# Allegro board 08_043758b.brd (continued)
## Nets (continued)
GND: C1.2(N2) C2.2(N2) C3.2(N2) C4.2(N2) C5.2(N2) C6.2(N2) C7.1 C8.2(N2) C9.2(N2) C10.2(N2) C11.2(N2) C12.2(N2) C13.2(N2) C14.2(N2) C15.2(N2) C16.2(N2) C17.2(N2) C18.2(N2) C19.2(N2) C20.2(N2) C21.2(N2) C22.2(N2) C23.2(N2) C24.2(N2) C25.2(N2) C26.2(N2) C27.2(N2) C28.2(N2) C29.2(N2) C30.2(N2) C31.2(N2) C32.2(N2) C33.2(N2) C34.2(N2) C35.2(N2) C36.2(N2) C37.2(N2) C38.2(N2) C39.2(N2) C40.2(N2) C41.2(N2) C42.2(N2) C43.2(N2) C44.2(N2) C45.2(N2) C46.2(N2) C47.2(N2) C48.2(N2) C49.2(N2) C50.2(N2) C51.2(N2) C52.2(N2) C53.2(N2) C54.2(N2) C55.2(N2) C56.2(N2) C57.2(N2) C58.2(N2) C59.2(N2) C60.2(N2) C61.2(N2) C62.1 C63.1 C64.2(N2) C65.2(N2) C66.2(N2) C67.2(N2) C68.2(N2) C69.2(N2) C70.2(N2) C71.2(N2) C72.2(N2) C73.2(N2) C74.2(N2) C75.2(N2) C76.2(N2) C77.2(N2) C78.2(N2) C79.2(N2) C80.2(N2) C81.2(N2) C82.2(N2) C83.2(N2) C84.2(N2) C85.2(N2) C86.2(N2) C87.2(N2) C88.2(N2) C89.2(N2) C90.2(N2) C91.2(N2) C92.2(N2) C94.2(N2) C95.2(N2) C96.2(N2) C97.2(N2) C99.1 C100.2(N2) C101.2(N2) C102.2(N2) C103.2(N2) C104.2(N2) C105.2(N2) C106.2(N2) C107.2(N2) C108.2(N2) C109.2(N2) C110.2(N2) C111.2(N2) C112.2(N2) C113.2(N2) C114.2(N2) C115.2(N2) C116.2(N2) C117.2(N2) C118.2(N2) C119.2(N2) C120.2(N2) C121.2(N2) C122.2(N2) C124.2(N2) C125.1 C126.1 C127.2(N2) C128.2(N2) C129.1 C130.2(N2) C135.2(N2) C136.2(N2) C137.2(N2) C138.2(N2) C139.1 C140.2(N2) C141.2(N2) C142.1 C143.1 C145.2(N2) C146.2(N2) C147.1 C148.2(N2) C149.2(N2) C150.2(N2) C151.2(N2) C152.2(N2) C153.2(N2) C154.2(N2) C155.2(N2) C156.2(N2) C157.2(N2) C158.2(N2) C159.2(N2) C160.2(N2) C161.2(N2) C162.2(N2) C163.1 C164.2(N2) C165.2(N2) C166.1 C167.2(N2) C168.2(N2) C169.2(N2) C170.2(N2) C173.2(N2) C174.2(N2) C178.2(N2) D1.A(P) D2.A(P) D3.A(P) E6.1 GND.1 GND#2.1 GND#3.1 GND#4.1 L7.3 P1.7 P1.9 Q1.2(S) Q4.2(S) R2.1 R3.1 R9.2(N2) R15.2(N2) R40.2(N2) R42.2(N2) R49.1 R53.1 R54.2(N2) R61.1 R63.2(N2) R65.1 R72.2(N2) R75.2(N2) R77.2(N2) R90.2(N2) R91.2(N2) R116.2(N2) R119.2(N2) R120.2(N2) R121.2(N2) R165.2(N2) RX1A.2 RX1A.3 RX1A.4 RX1A.5(SH4) S1.3 S1.4 T1.1 T1.2 T1.5 T5.1 T5.2 T5.5 TX1A.2 TX1A.3 TX1A.4 TX1A.5(SH4) U1.6 U1.PAD U2.A9 U2.B1 U2.B3 U2.B9 U2.D1 U2.D8 U2.E1 U2.E2 U2.E8 U2.F9 U2.G1 U2.G8 U2.G9 U2.J2 U2.J8 U2.M1 U2.M9 U2.P1 U2.P9 U2.T1 U2.T9 U3.5 U3.6 U3.7 U3.8 U3.PAD U4.A1 U4.A11 U4.B8 U4.C5 U4.C15 U4.D2 U4.D12 U4.E5 U4.E7 U4.E8 U4.E9 U4.F10 U4.G3 U4.G5 U4.G13 U4.H6 U4.H8 U4.H10 U4.J5 U4.J9 U4.K4 U4.K7 U4.K10 U4.K14 U4.L1 U4.L5 U4.L11 U4.M8 U4.N5 U4.N15 U4.P2 U4.P12 U4.R9 U5.A1 U5.A2 U5.A4 U5.A5 U5.A6 U5.A12 U5.B1 U5.B2 U5.B12 U5.C1 U5.C2 U5.C4 U5.C7 U5.C8 U5.C9 U5.C10 U5.C11 U5.C12 U5.D1 U5.D12 U5.E1 U5.F1 U5.F3 U5.F7 U5.F9 U5.F11 U5.G1 U5.G10 U5.G12 U5.H1 U5.H2 U5.H3 U5.H5 U5.H6 U5.H7 U5.H9 U5.H10 U5.J1 U5.J2 U5.K1 U5.K2 U5.K12 U5.L1 U5.L2 U5.L3 U5.L7 U5.L8 U5.L9 U5.L10 U5.L11 U5.L12 U5.M4 U5.M5 U5.M6 U6.1 U6.19 U6.20 U6.21 U6.22 U6.PAD U7.6 U7.PAD U10.4 U11.4 U12.3 U12.PAD U13.B3 U14.4 U14.8 U14.PAD U15.PAD Y1.2 Y2.2 Y3.2
PGND: C171.2(N2) C172.2(N2) L7.4(N4) P2.5 P3.5 Q2.2(S) R55.2(N2) R58.2(N2) R67.2(N2) R69.2(N2) U8.C1 U9.C1 U16.B2
VCCPINT: C17.1 C19.1 C20.1 C21.1 C64.1 C66.1 C68.1 C70.1 C71.1 C72.1 C73.1 C74.1 C75.1 L4.2(N2) R7.2(N2) U4.E10 U4.F9 U4.G6 U4.G10 U4.H5 U4.J10 U4.K5 U4.L10 UNK1P0V.1
VCCPLL: C85.1 C178.1 E1.2(N2) U4.F5(VCCPLL)
VDD33_USB: C165.1 U15.20
VDD_INTERFACE: C32.1 C33.1 C38.1 C43.1 C44.1 C45.1 E4.2(N2) U5.H12
VDDA1P1_RX_VCO: C125.2(N2) R51.2(N2) U5.G2 U5.G3
VIN: C8.1 C9.1 C11.1 C62.2(N2) C135.1 C136.1 C137.1 C138.1 C157.1 C164.1 C167.1 C169.1 DS1.A(P) DS2.A(P) E2.1 Q3.2(S) R1.2(N2) R6.1 R56.1 R59.2(N2) R80.1 R81.1 R85.1 R221.1 R222.1 U3.12 U3.13 U6.14 U6.15 U6.16(VIN6) U6.25 U6.26 U6.27 U11.8(VCCB) U14.10 U15.21
VIN_5V_USB: L7.1 U8.A1 U8.B1(OUT2) U9.A1 U9.B1(OUT2)
VIN_5V_USB_DATA: F1.2(N2) P2.1 R70.1 U9.A2 U9.B2
VIN_5V_USB_POWER: P3.1 R66.1 R68.1 U8.A2 U8.B2 U16.A1
1P3_SUPPLY_A: C14.1 C15.1 C16.1 C18.1 C23.1 C24.1 C28.1 C29.1 C34.1 C35.1 C39.1 C40.1 U5.B9 U5.B10 U5.E2 U5.F2 U5.J3 U5.K3 U7.9 U7.10 U7.11 U7.12 U7.13 U7.14(VOUT5) UNK1P3V_A.1
1P3_SUPPLY_B: C3.1 C4.1 C5.1 C6.1 C26.1 C27.1 C30.1 C31.1 C36.1 C37.1 C41.1 C42.1 C129.2(N2) C130.1 E3.2(N2) L8.1 L9.1 U1.9 U1.10 U1.11 U1.12 U1.13 U1.14(VOUT5) U5.A7 U5.A8 U5.A9 U5.A10 U5.B8 U5.D2 U5.D3 U5.E3 U5.F12 U5.K4 U5.M9 U5.M10 UNK1P3V_B.1
1P8V_CLK: C121.1 C122.1 C170.1 U12.1(VOUT) UNK1P8V_CLK.1 Y3.4(VDD)
AD9363_AUXADC: ADC.1(N1) U5.L5
AD9363_AUXDAC1: DAC1.1(N1) U5.B3
AD9363_AUXDAC2: DAC2.1(N1) U5.C3
AD9363_GPO_0: GPO0.1(N1) U5.B7
AD9363_GPO_1: GPO1.1(N1) U5.B6
AD9363_GPO_2: GPO2.1(N1) U5.B5
AD9363_GPO_3: GPO3.1(N1) U5.B4
ADM1177_SCL: R81.2(N2) U10.6 U11.7
ADM1177_SDA: R80.2(N2) U10.7 U11.6
ADP2114_VIN: C141.1 R56.2(N2) U6.4 U6.8 U6.10 U6.31
COMP_1P8V: C142.2(N2) R60.1 U6.2
COMP_1P35V: C143.2(N2) C144.1 U6.7
CTRL_IN0: U4.F13 U5.C5
CTRL_IN1: U4.F14 U5.C6
CTRL_IN2: U4.G15 U5.D6
CTRL_IN3: U4.F15 U5.D5
DDR3_A0: R16.1 U2.N3 U4.P1
DDR3_A1: R22.1 U2.P7 U4.N1
DDR3_A2: R17.1 U2.P3 U4.M1
DDR3_A3: R23.1 U2.N2 U4.M4
DDR3_A4: R18.1 U2.P8 U4.P3
DDR3_A5: R24.1 U2.P2 U4.P4
DDR3_A6: R19.1 U2.R8 U4.P5
DDR3_A7: R25.1 U2.R2 U4.M5
DDR3_A8: R20.1 U2.T8 U4.P6
DDR3_A9: R26.1 U2.R3 U4.N4
DDR3_A10: R21.1 U2.L7 U4.J1
DDR3_A11: R27.1 U2.R7 U4.L2
DDR3_A12: R28.1 U2.N7 U4.M2
DDR3_A13: R34.1 U2.T3 U4.K2
DDR3_A14: R29.1 U2.T7 U4.K1
DDR3_BA0: R35.1 U2.M2 U4.M6
DDR3_BA1: R30.1 U2.N8 U4.R1
DDR3_BA2: R36.1 U2.M3 U4.N6
DDR3_CAS#: R32.1 U2.K3 U4.R5
DDR3_CK_N: R142.2(N2) U2.K7 U4.N2
DDR3_CK_P: R142.1 U2.J7 U4.N3
DDR3_CKE: R38.1 U2.K9 U4.L3
DDR3_CS#: R39.1 U2.L2 U4.R2
DDR3_DM0: U2.E7 U4.B1
DDR3_DM1: U2.D3 U4.D3
DDR3_DQ0: U2.E3 U4.D4
DDR3_DQ1: U2.F7 U4.A2
DDR3_DQ2: U2.F2 U4.C4
DDR3_DQ3: U2.F8 U4.C1
DDR3_DQ4: U2.H3 U4.B4
DDR3_DQ5: U2.H8 U4.A4
DDR3_DQ6: U2.G2 U4.C3
DDR3_DQ7: U2.H7 U4.A3
DDR3_DQ8: U2.D7 U4.E1
DDR3_DQ9: U2.C3 U4.D1
DDR3_DQ10: U2.C8 U4.E2
DDR3_DQ11: U2.C2 U4.E3
DDR3_DQ12: U2.A7 U4.F3
DDR3_DQ13: U2.A2 U4.G1
DDR3_DQ14: U2.B8 U4.H1
DDR3_DQ15: U2.A3 U4.H2
DDR3_DQS0_N: U2.G3 U4.B2
DDR3_DQS0_P: U2.F3 U4.C2
DDR3_DQS1_N: U2.B7 U4.F2
DDR3_DQS1_P: U2.C7 U4.G2
DDR3_ODT: R33.1 U2.K1 U4.K3
DDR3_RAS#: R37.1 U2.J3 U4.R6
DDR3_RST#: R42.1 U2.T2 U4.L4
DDR3_WE#: R31.1 U2.L3 U4.R3
FB0: R2.2(N2) R4.1 U3.4
FB_1P8V: R64.1 R65.2(N2) U6.32
FB_1P35V: R62.2(N2) R63.1 U6.9
IO_02_34_AD9361_CLKOUT: AD9361_CLKOUT.1(N1) U4.P8 U5.J6
IO_02_34_AD9361_RST: U4.P9 U5.K5
IO_L01_34_FB_CLK: U4.P10 U5.F10
IO_L01_34_RX_D0: U4.H14 U5.K11
IO_L01_34_RX_D1: U4.J13 U5.J12
IO_L02_34_RX_D2: U4.G14 U5.K10
IO_L02_34_RX_D3: U4.H13 U5.J11
IO_L03_34_RX_D4: U4.G12 U5.K9
IO_L03_34_RX_D5: U4.H12 U5.J10
IO_L04_34_RX_D6: U4.G11 U5.K8
IO_L04_34_RX_D7: U4.J14 U5.J9
IO_L05_34_RX_D8: U4.J15 U5.K7
IO_L05_34_RX_D9: U4.K15 U5.J8
IO_L06_34_RX_D10: U4.H11 U5.J7
IO_L06_34_RX_D11: U4.J11 U5.H8
IO_L07_34_RX_FRAME: U4.N13 U5.G8
IO_L08_34_CTRL_OUT0: U4.L15 U5.D4
IO_L08_34_CTRL_OUT1: U4.M15 U5.E4
IO_L09_34_TX_FRAME: U4.L14 U5.G9
IO_L10_34_EN_AGC: U4.L13 U5.G5
IO_L11_34_ENABLE: U4.K12 U5.G6
IO_L11_34_TXNRX: U4.K11 U5.H4
IO_L12_MRCC_34_DATA_CLK: U4.L12 U5.G11
IO_L13_34_CTRL_OUT2: U4.N11 U5.E5
IO_L13_34_CTRL_OUT3: U4.N12 U5.E6
IO_L15_34_TX_D0: U4.P15 U5.E12
IO_L15_34_TX_D1: U4.R13 U5.D11
IO_L16_34_TX_D2: U4.R15 U5.E11
IO_L16_34_TX_D3: U4.P11 U5.D10
IO_L17_34_TX_D4: U4.R11 U5.E10
IO_L17_34_TX_D5: U4.R12 U5.D9
IO_L18_34_TX_D6: U4.P14 U5.E9
IO_L18_34_TX_D7: U4.P13 U5.D8
IO_L19_34_TX_D8: U4.N9 U5.E8
IO_L19_34_TX_D9: U4.M9 U5.D7
IO_L20_34_TX_D10: U4.R8 U5.F8
IO_L20_34_TX_D11: U4.R7 U5.E7
IO_L21_34_CTRL_OUT4: U4.M10 U5.F6
IO_L21_34_CTRL_OUT5: U4.M11 U5.F5
IO_L22_34_CTRL_OUT6: U4.N7 U5.F4
IO_L22_34_CTRL_OUT7: U4.N8 U5.G4
IO_L23_35_SPI_CLK: U4.E11 U5.J5
IO_L23_35_SPI_ENB: U4.E12 U5.K6
IO_L24_35_SPI_DI: U4.E13 U5.J4
IO_L24_35_SPI_DO: U4.F12 U5.L6
JTAG_TCK: P1.4 TCK.1(N1) U4.G9
JTAG_TDI: P1.8 TDI.1(N1) U4.L7
JTAG_TDO: P1.6 TDO.1(N1) U4.L8
JTAG_TMS: P1.2 TMS.1(N1) U4.L9
PG_1P0V: R6.2(N2) R86.1 U3.16
PG_1P3V: C47.1 PG_1P3V.1(N1) R13.2(N2) R15.1 U1.5 U4.C9 U7.5 U12.4
PG_1P8V: R59.1 U6.13 U6.29
PG_1P35V: R50.1 U1.4 U6.12 U7.4
PL_GPIO0: L10P.1(N1) U4.K13
PL_GPIO1: L12N.1(N1) U4.M12
PL_GPIO2: L24N.1(N1) U4.R10
PS-SRST#: R74.2(N2) U4.B11 U13.A4
PS_GPIO0: MIO0.1(N1) U4.D8
PS_GPIO1: MIO10.1(N1) U4.B10
PS_GPIO2: MIO11.1(N1) U4.D6
PS_GPIO3: MIO09.1(N1) U4.B5
PS_GPIO4: MIO53.1(N1) U4.C13
PS_GPIO5: MIO49.1(N1) U4.D13
PS_GPIO6: MIO48.1(N1) U4.B12
PS_MIO01_500_QSPI0_SS_B: R14.2(N2) U4.A5 U13.C2
PS_MIO02_500_QSPI0_IO0: R120.1 U4.A8 U13.D3
PS_MIO03_500_QSPI0_IO1: R119.1 U4.A7 U13.D2
PS_MIO04_500_QSPI0_IO2: R121.1 U4.C8 U13.C4(W#DQ2)
PS_MIO05_500_QSPI0_IO3: JTAG_BOOT.1(N1) P1.5 R122.1 U4.A9 U13.D4
PS_MIO06_500_QSPI0_SCLK: R116.1 U4.A10 U13.B2
PS_MIO07_500_USB_RESET_B: R76.2(N2) U4.A12 U15.27
PS_MIO28_501_USB0_D4: U4.A15 U15.7
PS_MIO29_501_USB0_DIR: U4.D11 U15.31
PS_MIO30_501_USB0_STP: U4.B15 U15.29
PS_MIO31_501_USB0_NXT: U4.C12 U15.2
PS_MIO32_501_USB0_D0: U4.E15 U15.3
PS_MIO33_501_USB0_D1: U4.C11 U15.4
PS_MIO34_501_USB0_D2: U4.D15 U15.5
PS_MIO35_501_USB0_D3: U4.A14 U15.6
PS_MIO36_501_USB0_CLK: U4.B14 U15.1
PS_MIO37_501_USB0_D5: U4.C14 U15.9
PS_MIO38_501_USB0_D6: U4.A13 U15.10
PS_MIO39_501_USB0_D7: U4.D14 U15.13
PWR_CLK: R5.2(N2) R89.2(N2) R90.1 U3.1
RX1A_N: C133.2(N2) U5.M2
RX1A_P: C134.2(N2) U5.M1
SCL: R79.2(N2) U4.M14 U11.2
SDA: R78.2(N2) U4.N14 U11.3
SYNC: L4.1 U3.9 U3.10 U3.11
TX1A_N: C131.1 L8.2(N2) U5.M8
TX1A_P: C132.1 L9.2(N2) U5.M7
TX_VCO_1P1V_SUPPLY: C128.1 R52.1 U5.A11 U5.B11
UART_RX: P1.1 RX.1(N1) U4.C6
UART_TX: P1.3 TX.1(N1) U4.B7
UNNAMED_2_ADM7160V2_I254_VIN: C173.1 E2.2(N2) U12.6
UNNAMED_2_ADP1754_I93_SS: C2.1 U1.7
UNNAMED_2_ADP1754_I233_SS: C12.1 U7.7
UNNAMED_2_ADP2164_I29_EN: C13.1 R1.1 R5.1 R10.1 U3.3 U3.14(VIN) U3.15
UNNAMED_2_ADP2164_I29_RT: R3.2(N2) R10.2(N2) U3.2
UNNAMED_2_FERRITE_I303_N1: E3.1 VDD_GPO.1(N1)
UNNAMED_2_RES_I251_N2: R4.2(N2) R7.1
UNNAMED_3_ICXC7Z010_I16_PSCLK50: R12.2(N2) U4.C7
UNNAMED_3_ICXC7Z010_I16_PSMIO75: R83.2(N2) U4.D9
UNNAMED_3_ICXC7Z010_I16_PSMIO85: R84.1 U4.B6
UNNAMED_3_RES_I2_N1: R8.2(N2) R9.1 Y2.1
UNNAMED_3_RES_I48_N1: R12.1 Y2.3
UNNAMED_4_ICMT41K256M16_I98_ZQ: R165.1 U2.L8(ZQ)
UNNAMED_4_ICTPS51206_I44_S3: R222.2(N2) U14.7
UNNAMED_4_ICTPS51206_I44_S5: R221.2(N2) U14.9
UNNAMED_4_ICTPS51206_I44_VLDOIN: R44.2(N2) U14.2
UNNAMED_4_ICTPS51206_I44_VTTSNS: C80.1 R43.2(N2) U14.5(VTTSNS)
UNNAMED_4_ICXC7Z010_I26_PSDDR_1: R40.1 U4.H3
UNNAMED_4_ICXC7Z010_I26_PSDDRVR: R41.1 U4.J3
UNNAMED_5_CAP_I17_N1: C93.1 C98.1 E5.2(N2) U4.F7
UNNAMED_5_CAP_I17_N2: C93.2(N2) C98.2(N2) E6.2(N2) U4.F6 U4.F8 U4.G8 U4.H7 U4.J7
UNNAMED_5_DIOLED_I60_N: DS1.C R48.1
UNNAMED_5_DIOLED_I62_N: DS2.C R87.1
UNNAMED_5_ICXC7Z010_I13_DONE0: Q1.1 U4.M7
UNNAMED_5_ICXC7Z010_I13_INITB0: R47.1 U4.D5
UNNAMED_5_ICXC7Z010_I13_PROGRAM: R46.1 U4.K6
UNNAMED_5_ICXC7Z010_I13_VCCBATT: R45.2(N2) U4.E6
UNNAMED_5_ICXC7Z010_I13_VP0: R11.2(N2) R91.1 U4.G7
UNNAMED_5_RES_I61_N2: Q1.3 R48.2(N2)
UNNAMED_5_RES_I63_N2: Q4.3 R87.2(N2)
UNNAMED_7_AD9363_I13_RBIAS: R49.2(N2) U5.L4
UNNAMED_7_AD9363_I13_XTALN: C123.2(N2) C124.1 U5.M12(XTALN)
UNNAMED_7_CAP_I22_N2: C126.2(N2) R51.1
UNNAMED_7_CAP_I30_N1: C127.1 R52.2(N2)
UNNAMED_7_CAP_I39_N2: C132.2(N2) T5.4
UNNAMED_7_CAP_I40_N2: C131.2(N2) T5.6(SEC_DOT)
UNNAMED_7_CAP_I51_N1: C134.1 T1.4
UNNAMED_7_CAP_I52_N1: C133.1 T1.6(SEC_DOT)
UNNAMED_7_CAP_I53_N1: C123.1 Y3.3
UNNAMED_7_CNBNC5P_I57_CNTR: RX1A.1 T1.3
UNNAMED_7_CNBNC5P_I58_CNTR: T5.3 TX1A.1
UNNAMED_9_ADM1177_I23_GATE: Q3.1 U10.10
UNNAMED_9_ADM1177_I23_ON: R71.2(N2) R72.1 U10.3
UNNAMED_9_ADM1177_I23_SENSE: Q3.3 R73.2(N2) U10.2
UNNAMED_9_ADM1177_I23_SS: C155.1 U10.9
UNNAMED_9_ADM1177_I23_TIMER: C156.1 U10.5
UNNAMED_9_ADM1177_I23_VCC: D3.C L7.2 R71.1 R73.1 U10.1(VCC)
UNNAMED_9_ADP198_I329_VOUT: C171.1 C172.1 F1.1 R88.1 U16.A2(VOUT)
UNNAMED_9_ADP2114_I196_EN1: R85.2(N2) R86.2(N2) U6.28
UNNAMED_9_ADP2114_I196_FREQ: R53.2(N2) U6.3
UNNAMED_9_ADP2114_I196_OPCFG: R54.1 U6.6
UNNAMED_9_ADP2114_I196_SS1: C7.2(N2) U6.30
UNNAMED_9_ADP2114_I196_SS2: C139.2(N2) U6.11
UNNAMED_9_ADP2114_I196_SW1: L3.1 R89.1 U6.23 U6.24
UNNAMED_9_ADP2114_I196_SW3: L2.1 U6.17 U6.18
UNNAMED_9_CAP_I163_N1: C146.1 L3.2(N2) L5.1
UNNAMED_9_CAP_I214_N2: C147.2(N2) R60.2(N2)
UNNAMED_9_CAP_I224_N2: C144.2(N2) R61.2(N2)
UNNAMED_9_CHOKE4P_I327_N2: D1.C L6.2 P2.3
UNNAMED_9_CHOKE4P_I327_N3: D2.C L6.3 P2.2
UNNAMED_9_CN5P3SHLD_I255_N6: P2.SH1 P2.SH2 P2.SH3(N8) R55.1
UNNAMED_9_CN5P3SHLD_I256_N6: P3.SH1 P3.SH2 P3.SH3(N8) R58.1
UNNAMED_9_ICNCP339_I277_EN: R68.2(N2) R69.1 U8.C2
UNNAMED_9_ICNCP339_I278_EN: Q2.3 R70.2(N2) U9.C2
UNNAMED_9_RES_I270_N1: Q2.1 R66.2(N2) R67.1
UNNAMED_11_ICUSB3320C_I29_RBIAS: R77.1 U15.24
UNNAMED_11_ICUSB3320C_I29_REFCL: R82.1 U15.26
UNNAMED_11_RES_I67_N2: R82.2(N2) Y1.3
USB_ID: P2.4 U15.23
USB_OTG_CPEN: U15.17 U16.B1
USB_OTG_N: L6.4(N4) U15.19
USB_OTG_P: L6.1 U15.18
USB_VBUS_OTG: R88.2(N2) U15.22
USR_BTN: R57.2(N2) S1.1 U4.B9
USR_LED: Q4.1 R75.1 U4.D10
VTT_0P75: C79.1 C101.1 R16.2(N2) R17.2(N2) R18.2(N2) R19.2(N2) R20.2(N2) R21.2(N2) R22.2(N2) R23.2(N2) R24.2(N2) R25.2(N2) R26.2(N2) R27.2(N2) R28.2(N2) R29.2(N2) R30.2(N2) R31.2(N2) R32.2(N2) R33.2(N2) R34.2(N2) R35.2(N2) R36.2(N2) R37.2(N2) R38.2(N2) R39.2(N2) R43.1 U14.3
VTTVREF: C63.2(N2) C81.1 C84.1 C99.2(N2) C102.1 U2.H1 U2.M8 U4.F4 U14.6

Pads without a net: P3 2 3 4; S1 2 5; U1 8; U2 J1 J9 L1 L9 M7; U5 A3 G7 H11 M3 M11; U6 5; U7 8; U10 8; U11 5; U12 2 5; U13 A2 A3 A5 B1 B5 C1 C3 C5 D1 D5 E1 E2 E3 E4 E5; U15 12 15 16 25; Y1 1; Y3 1

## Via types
v1: diameter 0.508, hole 0.254, TOP to BOTTOM, 784 vias
v2: diameter 0.406, hole 0.203, TOP to BOTTOM, 592 vias

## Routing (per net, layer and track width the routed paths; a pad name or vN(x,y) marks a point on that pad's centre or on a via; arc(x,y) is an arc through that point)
1V8: length 131.4
  TOP w0.203: 41.57,9.21 41.69,9.09
  TOP w0.305: 41.57,9.21 U7.3 U7.2 ; 19.33,9.21 U1.2 ; U1.2 U1.1 ; U1.2 U1.3 19.98,9.21 ; U1.1 18.68,9.21 ; U1.1 18.25,9.98 ; U4.J6 v2(53.13,35.35) ; C25.1 31.94,12.27 ; C25.1 31.53,11.81 ; C25.1 31.53,12.72 ; U15.32 74.8,28.62 v1(74.27,29.16) ; R74.1 65.25,29.78 v1(65.25,29.54) ; U7.2 40.92,9.21 ; U7.2 U7.1 ; U11.1 56.97,15.84 C166.2 56.42,16.84 v1(56.6,17.02) ; 16.98,10.91 U1.16 ; U1.16 17.76,10.48 ; U1.16 U1.15 ; U15.14 77.3,22.44 v1(77.44,22.3) ; U4.H4 v2(54.73,36.95) ; C1.1 19.98,8.91 ; C1.1 19.98,8 ; C1.1 19.57,8.46 ; U7.16 U7.15 ; U7.16 39.35,10.48 ; U7.16 38.57,10.91 ; U4.E14 v2(57.13,28.15) ; v1(54.93,15.25) R79.1 ; U4.M13 v2(50.73,28.95) ; v1(55.34,12.77) 55.61,13.04 R78.1 ; 41.16,8.46 C10.1 ; C10.1 41.57,8.91 ; C10.1 41.57,8 ; U4.J8 v2(53.13,33.75) ; U15.11 v1(75.8,22.31) ; U4.C10 v2(58.73,31.35) ; U15.8 v1(74.1,23.44) ; R47.2 v1(65.12,39.23) ; U4.H9 v2(53.93,32.95) ; 81.51,31.82 UNK1V8.1 ; UNK1V8.1 81.51,33.35 ; UNK1V8.1 82.27,32.59 ; Y2.4 70.4,34.62 C46.1 71.54,35.19 v1(71.47,35.25) ; R84.2 66.64,38.43 v1(67.54,38.43) ; U4.J4 v2(53.13,36.95) ; U4.L6 v2(52.33,34.55) ; U4.N10 v2(49.93,31.35) ; v1(76.81,29.28) 76.8,29.28 U15.28 ; U4.B13 v2(59.53,28.95) ; U4.H15 v2(54.33,27.15) ; U4.P7 v2(49.13,34.55) ; U4.F11 v2(56.33,30.55) ; v1(75.79,29.28) 75.8,29.27 U15.30 ; 39.84,9.98 U7.1 ; U7.1 40.27,9.21 ; v1(78.97,35.89) C163.2 78.4,34.54 Y1.4 ; U13.B4 v2(73.61,45.31) ; U4.K9 v2(52.33,32.95) ; U4.J12 v2(53.13,29.75) ; U4.D7 v2(57.93,34.55) ; U4.G4 v2(55.53,36.95) ; U4.R14 v2(48.33,28.15) ; R8.1 v1(72.6,36.9) ; U4.A6 v2(60.43,34.95) ; U4.K8 v2(52.33,33.75)
  TOP w0.508: R44.1 41.3,50.89 ; R44.1 40.18,50.89 ; R44.1 40.74,50.33
  TOP w0.635: 32.42,9.66 C22.1 ; C22.1 33.06,10.36 ; C22.1 32.42,11.06 ; E4.1 34.14,12.2 ; E4.1 32.36,12.2 ; E4.1 33.25,11.38
  TOP w0.762: C82.1 39.94,46.77 ; C82.1 40.74,45.92 ; C82.1 39.94,45.07 ; C83.1 39.94,49.57 ; C83.1 40.74,48.71 ; C83.1 39.94,47.86
  TOP w1.016: 81.76,35.15 L5.2 83.12,35.93
  TOP w1.27: 84.81,33.23 C150.1 ; C150.1 84.81,35.75 ; C150.1 83.75,34.49 ; 83.75,31.44 C149.1 84.81,32.7
  BOTTOM w0.203: 82.92,34.88 v1(82.9,34.87)
  BOTTOM w0.305: C162.1 59.23,30.85 v2(58.73,31.35) 59.03,31.65 59.34,31.65 C69.1 ; C161.1 56.91,28.36 v2(57.13,28.15) ; C111.1 59.64,28.35 R76.1 ; v2(57.14,25.64) 56.96,25.46 C117.1 ; C78.1 v2(46.62,32.56) C90.1 ; v2(73.61,45.31) 73.23,45.69 C48.1 ; R64.2 84.68,35.25 ; R50.2 v1(80.36,45.03) ; v1(75.79,29.28) C154.1 ; R45.1 60.93,33.65 60.61,33.97 C53.1 60.43,34.63 v2(60.43,34.95) 60.43,35.27 C52.1 ; v1(64.23,32.84) 64.14,32.75 R83.1 ; v2(54.33,27.15) 54.35,27.16 C119.1 ; R57.1 79.81,35.89 v1(78.97,35.89) ; R13.1 73.16,32.79 v1(73.16,33.6) ; C120.1 49.13,33.85 ; C110.1 50.82,29.04 v2(50.73,28.95) 50.63,28.85 C118.1 ; C168.1 v1(76.81,29.28) C140.1 ; R14.1 v1(75.54,47.57) ; C107.1 v2(59.83,25.64) C113.1 ; C108.1 v2(46.62,30.94)
  BOTTOM w0.406: C112.1 48.33,28.65 v2(48.33,28.15) 48.33,27.64 C114.1 ; v2(59.53,28.95) 59.53,28.95 C111.1 ; C115.1 v2(57.14,25.64) ; C67.1 v2(51.93,25.64) C106.1 ; v2(43.15,30.17) 43.15,30.95 C77.1 43.57,31.42 43.17,31.82 v2(43.17,32.59) ; 49.13,33.85 49.13,33.85 v2(49.13,34.55) 48.61,34.55 48.29,34.24 C51.1 ; v2(62.83,28.45) 62.83,27.8 C103.1 62.03,27.8 v2(62.03,28.45) 62.04,28.45 C160.1 v2(62.04,29.75) C159.1 62.04,30.94 v2(62.03,30.95) 62.04,30.95 C50.1 ; C105.1 v2(54.34,25.64) C109.1 ; R46.2 50.63,32.05 v2(49.93,31.35) 49.32,31.35 C116.1
  BOTTOM w0.508: v1(65.12,39.23) 65.92,39.23 R11.1 ; v2(46.71,24.73) 45.74,24.73 C104.1 45.38,24.71 v2(44.42,24.71) ; v1(44.04,34.24) 44.04,35.73 C76.1 v1(44.02,37.16) ; v1(70.58,42.75) R122.2 ; v2(49.63,24.71) 48.68,24.71 C65.1 48.31,24.73 v2(47.34,24.73)
  BOTTOM w0.635: v1(68.3,44.9) 67.66,44.9 67.03,44.27 E5.1 67.35,43.89 v1(68.3,43.89) ; E1.1 69.59,36.35 C174.1 69.59,38.15 v1(69.38,38.36) ; C152.1 84.87,34.81 ; C152.1 84.87,33.41 ; C152.1 84.24,34.11 ; 84.24,32.59 C153.1 ; C153.1 84.87,33.28 ; C153.1 84.87,31.89
  BOTTOM w0.762: 64.2,31.32 C49.1 ; C49.1 65.25,32.57 ; C49.1 65.25,30.06 ; 65.25,29.14 C158.1 64.2,27.89
  vias: v1(18.64,8.33) v1(18.64,7.69) v1(18.64,7.06) v1(19.28,8.33) v1(19.28,7.69) v1(19.28,7.06) v1(19.91,7.69) v1(19.91,7.06) v1(33.5,11) v1(33.5,10.36) v1(33.5,9.73) v1(34.14,11) v1(34.14,10.36) v1(34.14,9.73) v1(39.6,47.32) v1(40.23,8.33) v1(40.23,7.69) v1(40.23,7.06) v1(40.49,47.32) v1(40.87,8.33) v1(40.87,7.69) v1(40.87,7.06) v1(41.37,49.35) v1(41.37,48.33) v1(41.37,47.32) v1(41.37,46.3) v1(41.37,45.29) v1(41.5,7.69) v1(41.5,7.06) v1(64.49,29.54) v1(64.88,32.84) v1(65.52,32.84) v1(65.89,29.54) v1(82.9,34.11) v1(82.9,33.35) v1(82.9,32.59) v1(82.9,31.82) v1(82.9,31.06) v1(83.54,34.87) v1(83.54,34.11) v1(83.54,33.35) v1(83.54,32.59) v1(83.54,31.82) v1(83.54,31.06)
1V35: length 42.4
  TOP w0.203: U14.1 39.22,52.23 39.34,52.11 v1(39.34,51.64)
  TOP w0.305: U2.B2 v2(60.82,55.07) ; U2.R9 v2(50.42,49.47) ; 81.63,55.45 UNK1V35.1 80.87,54.68 ; U4.E4 v2(57.13,36.95) ; U4.J2 v2(53.13,38.55) ; C60.1 63.22,38.07 v2(63.14,38.16) ; U2.H9 v2(55.22,48.67) ; U2.A1 v2(61.62,55.87) ; U2.G7 v2(56.82,51.07) ; U4.R4 v2(48.23,36.55) ; U2.K2 v2(53.62,55.07) ; U2.K8 v2(53.62,49.47) ; U2.F1 v2(57.62,55.87) ; U4.M3 v2(50.73,37.75) ; v2(55.53,39.35) 55.53,39.35 U4.F1 ; U2.D9 v2(58.42,48.67) ; U2.C9 v2(60.02,48.67) ; U2.D2 v2(59.22,55.07) ; v2(52.02,49.47) 51.62,49.07 U2.N9 ; U2.C1 v2(60.02,55.87) ; U2.A8 v2(61.62,49.47) ; U2.R1 v2(49.62,55.87) ; U2.E9 v2(57.62,48.67) ; U2.N1 v2(51.22,55.87) ; U2.H2 v2(56.02,55.07) ; U4.B3 v2(59.53,37.75)
  TOP w0.406: v2(51.73,42.15) 52.23,42.15 C58.1 ; C56.1 v1(45.82,35.27) ; v2(53.53,42.15) 54.03,42.15 C57.1
  TOP w0.635: 83.35,55.32 C151.1 83.98,54.62
  TOP w1.016: C145.1 83.86,54.21 ; C145.1 83.86,52.11 ; C145.1 82.95,53.16 ; 65.63,53.5 C100.1 ; C100.1 66.89,54.56 ; C100.1 64.37,54.56 ; 82.95,50.75 C148.1 ; C148.1 83.86,51.8 ; C148.1 83.86,49.69
  BOTTOM w0.203: v1(83.92,49.48) 84.3,49.1 R62.1
  BOTTOM w0.305: v2(50.42,49.47) 50.11,49.47 C86.1 ; UNK1V35.1 v1(82.01,55.45) ; v2(56.82,51.07) 56.3,51.07 C92.1 ; R41.2 53.63,38.55 v2(53.13,38.55) ; v2(61.62,55.87) 61.62,56.47 C88.1 ; C97.1 61.7,49.39 v2(61.62,49.47) ; C95.1 57.71,55.96 v2(57.62,55.87) ; v2(53.62,55.07) 54.22,54.47 C89.1 ; C87.1 60.63,48.67 v2(60.02,48.67) ; C91.1 55.3,48.75 v2(55.22,48.67) ; C94.1 59.84,56.05 v2(60.02,55.87) ; v2(49.62,55.87) 49.53,55.95 C96.1 ; C61.1 47.52,36.34
  BOTTOM w0.406: 47.52,36.34 47.73,36.55 v2(48.23,36.55) ; v2(55.53,39.35) 55.53,39.35 55.53,39.76 C55.1 ; v2(53.13,38.55) 53.12,38.56 C59.1
  vias: v1(64.11,54.94) v1(64.11,53.92) v1(65.12,53.29) v1(66.14,53.29) v1(82.01,54.81) v1(82.01,54.18) v1(82.01,53.54) v1(82.01,52.91) v1(82.01,52.27) v1(82.65,55.45) v1(82.65,54.81) v1(82.65,54.18) v1(82.65,53.54) v1(82.65,52.91) v1(82.65,52.27) v2(56.11,43.57) v2(56.11,42.96)
GND: length 526.8
  TOP w0.152: U5.C7 32.34,32.08 v2(29.15,32.08) ; U5.H7 28.34,32.08 v2(26.75,32.08)
  TOP w0.203: U14.8 36.29,53.03 ; v1(101.83,33.98) 101.83,34.11 102.06,34.35 D1.A 102.46,33.98 ; U5.L7 26.13,31.47 26.13,31.09 U5.L8 ; v2(39.85,53.54) 39.74,53.43 U14.4 38.35,53.43 U14.PAD ; 101.32,36.02 D2.A 100.97,35.65 v1(100.7,35.93)
  TOP w0.305: GND#4.1 60.43,10.61 ; GND#4.1 59.66,9.85 ; GND#4.1 59.66,11.38 ; GND#4.1 58.9,10.61 ; C13.2 90.07,25.21 ; C13.2 88.95,25.21 ; C13.2 89.51,25.77 ; R9.2 71.6,38.14 ; R9.2 72.06,37.73 ; R9.2 71.14,37.73 ; v1(65.62,16.63) 65.44,16.46 C167.2 ; U2.B1 v2(60.82,55.87) ; 44.51,36.26 C56.2 ; C56.2 45.63,36.26 ; C56.2 45.07,36.82 ; C58.2 52.89,43.05 ; C58.2 51.77,43.05 ; C58.2 52.33,43.61 ; U6.19 89.14,45.02 88.8,44.68 ; U6.19 89.6,44.61 ; U6.19 90.3,45.02 ; C43.2 29.84,25.88 ; C43.2 29.46,27.09 29.55,27.17 29.6,27.17 ; C43.2 29.46,25.15 C45.2 ; 29.84,25.88 v1(30.05,25.67) ; 29.84,25.88 29.87,25.88 ; v1(34.77,53.1) 34.9,53.22 C84.2 35.6,53.03 36.29,53.03 ; U5.L7 v2(26.75,32.08) ; v2(33.14,27.28) U5.C12 v2(33.14,28.08) U5.C11 v2(33.14,28.88) U5.C10 v2(33.14,29.68) U5.C9 v2(33.14,30.48) U5.C8 v2(33.14,31.28) U5.C7 ; U5.H2 v2(28.35,36.08) U5.J2 ; 87.06,20.9 U3.6 ; U3.6 U3.7 ; U3.6 89.46,20.9 v2(89.78,20.57) 89.46,20.25 U3.7 ; U3.6 U3.5 ; C62.1 37.37,51.46 ; C62.1 37.37,50.54 ; C62.1 37.78,51 ; U4.R9 v2(48.25,32.55) ; U5.C2 v2(33.14,36.08) U5.B2 ; U2.T1 v2(48.82,55.87) 48.82,56.16 ; U4.A11 v2(60.53,30.95) ; U5.D1 v2(32.34,36.88) ; C12.2 45.13,11.57 ; C12.2 44.68,11.16 ; C12.2 44.05,11.57 v1(44.04,11.56) U7.6 41.57,11.56 v2(41.25,11.88) ; U4.B8 v2(58.73,33.75) ; U2.P1 v2(50.42,55.87) 50.42,56.18 ; 87.06,19.6 U3.8 ; U3.8 U3.7 ; U3.8 88.72,19.6 v2(88.76,19.56) ; C124.2 24.29,24.79 ; C124.2 24.29,23.87 ; C124.2 23.89,24.33 ; GND#3.1 35.34,65.22 ; GND#3.1 34.26,64.14 ; GND#3.1 33.18,65.22 ; GND#3.1 34.26,66.3 ; C167.2 65.85,16.01 ; C167.2 65.44,15.55 ; U5.D12 v2(32.34,27.28) ; U5.A4 v2(34.85,34.08) ; U6.22 88.94,43.52 88.8,43.66 ; U6.22 89.6,43.93 ; U6.22 90.3,43.52 ; U13.B3 v2(73.62,46.29) ; U4.E5 v2(57.13,36.15) ; C2.2 22.46,11.57 v1(22.45,11.56) U1.6 19.98,11.56 v2(19.66,11.88) ; C2.2 23.09,11.16 ; C2.2 23.54,11.57 ; U5.C4 v2(33.14,34.48) ; U2.E8 v2(58.42,49.47) ; 29.6,27.17 29.54,27.23 U5.G12 ; 29.6,27.17 29.62,27.17 v2(29.65,27.15) ; U2.J8 v2(55.22,49.47) ; U4.N5 v2(49.93,36.15) ; U4.E8 56.73,33.35 v2(56.33,33.75) U4.E7 ; U2.E2 v2(58.42,55.07) ; 22.11,34.62 R49.1 ; R49.1 22.52,34.16 ; R49.1 22.52,35.08 ; U3.5 88.72,21.55 v2(88.76,21.59) ; U3.5 87.06,21.55 ; U3.5 87.81,21.98 ; U3.7 87.06,20.25 ; U4.L11 v2(51.53,30.55) ; U5.L8 v2(25.95,30.48) U5.L9 v2(25.95,29.68) U5.L10 v2(25.95,28.88) U5.L11 v2(25.95,28.08) U5.L12 v2(25.95,27.28) 25.95,26.5 ; 30.49,12.27 C25.2 ; U5.F3 v2(30.74,35.28) ; 76.55,54.24 GND#2.1 ; GND#2.1 77.76,55.45 ; GND#2.1 76.55,56.65 ; GND#2.1 75.35,55.45 ; U5.K2 v2(26.74,36.08) U5.L2 ; U2.A9 v2(61.62,48.67) ; U5.E1 v2(30.74,36.88) U5.F1 ; 29.64,24.42 C45.2 ; C45.2 30.2,24.98 ; R61.1 98.2,42.5 ; R61.1 97.64,41.95 ; R61.1 97.08,42.5 ; C16.2 40.23,17.18 ; U4.P12 v2(49.13,29.75) ; C60.2 63.86,38.07 v2(63.94,38.16) ; 77.1,31.75 Y1.2 ; Y1.2 77.1,33.35 ; Y1.2 76.35,32.55 ; 17.55,38.19 T1.1 ; T1.1 18.8,38.2 ; T1.1 16.93,39.28 ; 102.36,11.26 Q4.2 ; Q4.2 104.27,11.26 ; Q4.2 103.31,12.02 ; Q4.2 103.31,10.5 ; 14.88,28.36 T5.1 ; 102.36,17.93 Q1.2 ; Q1.2 103.31,17.17 ; Q1.2 104.27,17.93 ; Q1.2 103.31,18.69 ; 72.17,34.16 C46.2 ; C46.2 72.58,34.62 ; C46.2 72.17,35.19 v1(72.24,35.25) ; U5.F9 v2(30.74,29.68) ; v2(60.33,39.35) U4.A1 ; U4.K7 v2(53.13,34.55) ; U5.H6 v2(28.35,32.88) ; U5.L1 v2(26.74,36.88) U5.K1 ; U5.M6 v2(25.14,32.88) U5.M5 ; U2.G8 v2(56.82,50.27) ; 93.38,6.8 GND.1 ; GND.1 95.79,6.8 ; GND.1 94.59,5.6 ; GND.1 94.59,8.01 ; v1(82.52,26.36) 82.27,26.11 C164.2 ; U4.C15 v2(58.33,27.24) ; 40.27,56.17 C79.2 ; C79.2 41.97,56.17 ; C79.2 41.12,56.97 ; 107.25,28.53 S1.4 108.03,27.58 ; U4.K10 v2(52.33,31.35) ; U4.K14 v2(53.13,28.94) ; 66.65,5.38 P1.7 ; U6.1 94.81,42.52 v1(95.35,41.98) ; U5.G10 v2(29.95,29.68) ; C1.2 v1(21.18,8.46) ; 54.13,43.6 C57.2 53.57,43.05 ; U4.M8 v2(50.73,33.75) ; 48.29,14 U12.3 47.61,14.41 ; 13.8,30.27 T5.2 ; C5.2 18.64,17.18 ; U5.K12 v2(26.74,27.28) ; 91.62,15.5 C8.2 91.16,15.1 ; U5.H9 v2(29.15,30.48) ; U4.C5 v2(58.73,35.35) ; 59.17,13.89 U11.4 v1(58.25,13.23) ; U4.N15 v2(50.33,27.25) ; U2.B9 v2(60.02,49.47) ; U4.E9 v2(57.13,32.15) ; U4.H6 v2(53.93,35.35) U4.J5 ; U5.L3 v2(25.95,35.28) ; v2(52.02,48.67) 52.42,49.07 U2.M9 ; U5.A2 v2(34.74,36.08) ; U4.H8 54.33,33.35 v2(53.93,33.75) ; 50.42,48.23 v2(50.42,48.67) U2.P9 ; U2.J2 v2(55.22,55.07) ; U2.D8 v2(58.42,50.27) ; U5.A5 v2(34.85,33.28) ; R75.2 101.57,14.53 ; R75.2 101.01,13.97 ; R75.2 102.13,13.97 ; U5.B12 v2(33.94,27.28) ; U2.G1 v2(56.82,55.87) ; U4.D2 v2(57.93,38.55) ; U4.G13 v2(55.53,28.95) ; U4.G5 v2(55.53,36.15) ; 77.76,36.35 C163.1 v1(77.23,35.89) ; U5.A6 v2(34.85,32.48) ; C33.2 31.21,17.09 v1(30.96,16.84) ; U5.B1 v2(33.14,36.88) U5.C1 ; 20.32,38.79 T1.5 ; U4.D12 v2(57.93,29.75) ; U5.A1 v2(34.74,36.88) ; U5.A12 v2(34.74,27.28) ; U5.J1 v2(28.35,36.88) U5.H1 ; 52.02,56.18 v2(52.02,55.87) U2.M1 ; C6.2 19.91,17.18 ; 55.38,16.39 C166.1 ; 107.25,23.03 S1.3 108.03,23.98 ; U4.J9 v2(53.13,32.95) ; 81.57,25.65 C164.2 ; C164.2 81.57,26.57 ; U5.H3 v2(28.35,35.28) ; U2.G9 v2(56.82,48.67) ; U5.H5 v2(28.35,33.68) ; U2.F9 v2(56.82,49.47) ; v1(62.33,34.11) 62.58,33.86 v1(65.14,33.86) v1(66.24,33.86) 70.8,33.86 v1(71.13,33.53) ; U4.P2 v2(49.13,38.55) ; U5.F7 v2(30.74,31.28) ; C122.2 26.1,16.08 ; 96.11,41.95 R53.1 96.67,42.5 ; U5.M4 v2(25.14,34.48) ; U2.T9 v2(48.82,48.67) 48.82,48.51 ; U2.B3 v2(60.82,53.47) ; C10.2 v1(42.77,8.46) ; U4.K4 v2(52.33,36.95) ; U2.E1 v2(58.42,55.87) ; U2.D1 v2(59.22,55.87) ; 67.92,5.38 P1.9 ; U4.L1 v2(51.93,39.45) ; U5.G1 v2(29.14,36.88) ; U4.L5 v2(51.53,36.15) ; C18.2 41.5,17.18 ; 17.57,40.38 T1.2 19.44,39.3 ; U4.H10 v2(54.73,31.35) ; U5.H10 v2(29.15,29.68) ; U5.F11 v2(30.74,28.08) ; U4.F10 v2(56.33,31.35) ; C141.2 97.55,46.81 ; U4.G3 v2(55.53,37.75) ; U5.H7 v2(29.15,32.08)
  TOP w0.406: v2(51.73,42.95) 52.23,42.95 C58.2 ; C57.2 53.93,42.85 v2(53.53,42.85)
  TOP w0.508: C121.2 27.53,14.55 ; C121.2 26.73,13.7 ; C121.2 26.73,15.4 ; C143.1 v1(96.86,44.54) ; 49.9,12.06 C169.2 ; C169.2 49.9,13.23 ; C169.2 49.35,12.65 ; 68.27,37.1 Y2.2 67.47,36.35 ; 46.58,14.02 C170.2 ; 56.43,20.58 C68.2
  TOP w0.635: 31.02,15.25 C32.2 ; C32.2 30.39,15.95 ; C32.2 31.02,16.65 ; 30.39,10.36 C22.2 31.02,9.66 ; v1(13.58,29) T5.1 v1(16.46,29) ; T1.5 19.89,39.04 ; 49.38,16.11 v1(49.38,15.06) 49.38,14.01 ; C3.2 14.9,15 ; C3.2 14.26,14.3 ; C3.2 14.9,13.6 ; v1(16.75,39.38) T1.1 v1(19.17,37.99) ; C4.2 17.82,17.41 ; C4.2 16.42,17.41 ; C4.2 17.12,18.04 ; v1(16.71,40.31) 16.88,40.48 17.4,40.48 T1.2 19.6,39.21 v1(19.71,38.81) ; 36.49,13.6 C15.2 ; C15.2 36.49,15 ; C15.2 35.85,14.3 ; C14.2 38.71,18.04 ; C14.2 38.01,17.41 ; C14.2 39.41,17.41 ; v1(13.07,29.71) 13.58,30.22 14.82,30.22 T5.2 16.13,30.27 v1(16.48,29.92) 16.83,30.27 T5.5 ; 49.57,16.65 C173.2 ; C173.2 48.93,17.35 ; C173.2 49.57,18.04 ; C9.2 93.38,15 ; C9.2 91.98,15 ; C9.2 92.68,14.36 ; 85.38,54.62 C151.2 86.02,55.32
  TOP w0.762: 60.64,19.7 C64.2 ; C64.2 63.16,19.7 ; C64.2 61.9,18.64 ; 37.44,45.92 C82.2 ; C82.2 38.24,46.77 ; C82.2 38.24,45.07 ; 27.81,20.07 Y3.2 26.96,21.02 ; C100.2 66.89,57.35 ; C100.2 65.63,58.41 ; C100.2 64.37,57.35 ; C19.2 77.57,20.6 ; C19.2 78.62,19.7 ; C19.2 76.52,19.7 ; C17.2 82.65,20.6 ; C17.2 81.6,19.7 ; C17.2 83.7,19.7 ; 88.17,39.7 C135.2 88.81,39 ; 88.17,37.92 C137.2 ; C137.2 88.81,37.22 ; C137.2 88.81,38.62 ; C54.2 61.27,43.06 ; C54.2 60.21,44.32 ; C54.2 60.21,41.81 ; 87.92,50.62 C138.2 ; C138.2 88.56,49.92 ; C138.2 88.56,51.32 ; 38.24,47.86 C83.2 ; C83.2 38.24,49.57 ; C83.2 37.44,48.71 ; C21.2 86.24,19.7 ; C21.2 84.14,19.7 ; C21.2 85.19,20.6 ; C71.2 59.9,19.76 ; C71.2 58.65,18.7 ; C71.2 57.39,19.76 ; C81.2 39.04,55.83 ; C81.2 38.14,54.77 ; C81.2 38.14,56.88 ; C20.2 81.16,19.7 ; C20.2 79.06,19.7 ; C20.2 80.11,20.6 ; 87.92,48.84 C136.2 88.56,49.54 ; C157.2 85.05,61.8 ; C157.2 83.79,62.85 ; C157.2 82.54,61.8 ; 37.95,54.04 U14.PAD v1(37.95,51.76)
  TOP w1.016: 85.76,52.11 C145.2 ; C145.2 85.76,54.21 ; C145.2 86.66,53.16 ; 85.76,51.8 C148.2 86.66,50.75 ; 94.97,13.84 C11.2 ; C11.2 93.91,14.74 ; C11.2 96.02,14.74 ; C146.2 87.73,37.67
  TOP w1.27: C149.2 88.66,31.44 ; C149.2 87.6,30.18 ; C149.2 87.6,32.7 ; C150.2 87.6,35.75 ; C150.2 87.6,33.23 ; C150.2 88.66,34.49 ; 92.38,54.81 D3.A ; D3.A 94.77,54.81 ; D3.A 93.57,53.41
  L5_SIG w0.305: GND#3.1 34.26,66.3 ; GND#3.1 33.18,65.22 ; GND#3.1 35.34,65.22 ; GND#3.1 34.26,64.14 ; 93.38,6.8 GND.1 ; GND.1 94.59,8.01 ; GND.1 94.59,5.6 ; GND.1 95.79,6.8 ; GND#4.1 60.43,10.61 ; GND#4.1 59.66,11.38 ; GND#4.1 58.9,10.61 ; GND#4.1 59.66,9.85 ; GND#2.1 76.55,56.65 ; GND#2.1 76.55,54.24 ; GND#2.1 77.76,55.45 ; GND#2.1 75.35,55.45
  L6_SIG w0.305: 58.9,10.61 GND#4.1 ; GND#4.1 59.66,9.85 ; GND#4.1 59.66,11.38 ; GND#4.1 60.43,10.61 ; 66.65,5.38 P1.7 ; 67.92,5.38 P1.9 68.71,6.17 ; 75.35,55.45 GND#2.1 ; GND#2.1 76.55,54.24 ; GND#2.1 76.55,56.65 ; GND#2.1 77.76,55.45 ; GND.1 95.79,6.8 ; GND.1 94.59,8.01 ; GND.1 93.38,6.8 ; GND.1 94.59,5.6 ; GND#3.1 34.26,66.3 ; GND#3.1 34.26,64.14 ; GND#3.1 33.18,65.22
  BOTTOM w0.305: v2(59.22,55.87) 59.21,55.88 C94.2 58.8,56.48 ; 77.84,28.19 R77.2 77.84,27.07 ; 55.17,40.95 C55.2 ; C55.2 55.73,41.51 ; C55.2 56.29,40.95 ; v1(46.84,57.48) 46.45,57.48 46.21,57.24 R42.2 ; 33.18,65.22 GND#3.1 ; GND#3.1 35.34,65.22 ; GND#3.1 34.26,64.14 ; GND#3.1 34.26,66.3 ; 53.27,41.25 R40.2 ; R40.2 53.63,41.05 v2(53.13,41.05) ; R40.2 54.39,41.25 ; C42.2 33.14,34.66 v2(33.14,34.48) ; R3.1 91.46,22.57 ; R3.1 90.9,22.01 ; R3.1 90.35,22.57 ; 37.7,26.37 C127.2 37.14,25.81 ; v1(88.11,25.09) R2.1 ; R2.1 87.55,24.32 ; R2.1 88.67,24.32 ; C91.2 55.3,49.39 v2(55.22,49.47) ; C91.2 55.82,49.8 ; C91.2 56.28,49.39 ; 60.43,30.85 60.46,30.85 ; 60.43,30.85 C162.2 60.05,30.39 ; 60.43,30.85 v2(60.53,30.95) ; 94.59,5.6 GND.1 ; GND.1 93.38,6.8 ; GND.1 95.79,6.8 ; GND.1 94.59,8.01 ; 56.08,24.83 C117.2 ; C117.2 56.53,24.42 ; C117.2 56.96,24.83 v2(57.14,24.65) ; 60.53,31.29 C69.2 61.09,31.85 ; 50.63,27.42 C118.2 50.17,27.83 ; 59.44,34.6 C178.2 58.88,35.16 ; 68.71,6.17 P1.9 67.92,5.38 ; 59.66,9.85 GND#4.1 ; GND#4.1 60.43,10.61 ; GND#4.1 58.9,10.61 ; GND#4.1 59.66,11.38 ; C36.2 25.04,32.85 ; C36.2 23.92,32.85 ; C36.2 24.48,32.29 ; 25.94,38.43 C29.2 25.38,37.87 ; C23.2 32.05,36.58 v2(32.34,36.88) ; 71.14,37.41 C174.2 70.58,37.97 ; 48.67,33.03 C120.2 49.13,32.63 ; C90.2 45.63,33.71 ; C90.2 45.07,33.15 ; C90.2 v2(45.63,32.56) C78.2 ; 78.98,22.34 C165.2 ; C165.2 79.83,23.14 ; C165.2 78.13,23.14 ; 58.97,27.25 C111.2 ; C111.2 59.53,26.69 ; C111.2 60.09,27.25 ; C114.2 47.43,28.11 ; C114.2 47.52,27.64 v2(47.52,28.14) 47.52,28.66 C112.2 47.43,29.34 47.43,29.34 ; C114.2 47.43,26.99 ; v2(30.74,35.28) C125.1 ; v1(77.57,31.05) C140.2 76.81,31.61 ; R72.2 92.39,56.66 ; R72.2 91.08,56.66 ; R72.2 91.83,56.1 ; GND#2.1 76.55,56.65 ; GND#2.1 77.76,55.45 ; GND#2.1 76.55,54.24 ; GND#2.1 75.35,55.45 ; C39.2 28.16,36.08 v2(28.35,36.08) ; 56.35,56.34 C63.1 56.76,55.88 ; 35.53,32.88 C31.2 34.97,32.32 ; 92.38,46.19 C139.1 ; C139.1 92.94,45.63 ; C139.1 93.5,46.19 ; 83.25,43.39 R90.2 ; R90.2 83.81,43.93 ; R90.2 84.37,43.39 ; 58.3,24.65 C115.2 57.74,24.09 ; C156.2 88.92,56.57 ; C156.2 88.37,56.01 ; C156.2 88.92,55.19 ; 52.72,32.61 C72.2 53.28,32.05 ; C44.2 29.46,28.14 ; C44.2 29.46,27.33 v2(29.65,27.15) 29.64,27.14 C38.2 29.64,25.91 ; C44.2 29.87,27.68 ; 60.73,50.12 C87.2 60.17,49.56 ; 60.53,24.09 C107.2 ; C107.2 v2(59.83,24.65) C113.2 ; C107.2 61.09,24.65 ; v2(48.82,48.67) 49.52,48.67 C86.2 49.92,48.67 v2(50.42,48.67) ; 56.53,27.32 C161.2 56.07,27.73 ; 94.46,43.34 R54.2 93.9,43.9 ; 54.63,31.39 C74.2 ; C74.2 54.63,32.51 ; C74.2 54.07,31.95 ; C119.2 54.35,26.53 v2(54.33,26.55) ; v1(94.59,39.76) C7.1 93.83,39.35 ; 33.95,33.82 C37.2 34.51,34.38 ; C26.2 31.77,26.68 ; C28.2 30.85,38.14 ; 40.23,55.92 C80.2 39.77,55.51 ; R15.2 71.27,32.65 C47.2 72.24,33.06 ; R15.2 70.66,32.7 ; R15.2 71.22,33.26 ; U10.4 v1(88.75,58.05) ; 49.22,29.89 C116.2 48.67,30.45 ; v1(53.72,44.87) R165.2 ; R65.1 93.95,42.91 ; R65.1 93.39,42.35 ; R65.1 94.51,42.35 ; 59.13,24.09 C113.2 ; C113.2 58.57,24.65 ; 72.65,46.33 C48.2 ; C48.2 73.59,46.33 v2(73.62,46.29) ; C48.2 73.11,46.73 ; 61.65,34.45 C53.2 61.25,34.91 ; 25.55,34.81 C41.2 26.01,35.21 v2(25.95,35.28) 25.83,35.4 25.62,35.4 ; 45.07,31.95 C78.2 ; C78.2 45.63,31.39 ; 51.33,24.09 C106.2 ; 30.3,38.67 C126.1 29.19,38.67 ; C88.2 60.82,56.49 v2(60.82,55.87) ; 74.19,50.1 R116.2 73.07,50.1 ; 55.59,24.65 C105.2 55.03,24.09 ; v2(33.14,30.48) 33.23,30.56 C27.2 33.23,31.2 v2(33.14,31.28) ; 25.62,35.4 C24.2 25.22,35.88 ; 25.62,35.4 25.62,35.38 ; 83.4,57.55 C155.2 83.96,56.77 ; 54.73,33.1 C70.2 54.17,33.66 ; 93.74,46.17 R63.2 94.14,45.84 93.76,45.46 93.3,45.46 v2(93.27,45.49) ; 95.57,41.73 C147.1 96.12,41.17 ; R121.2 72.16,43.52 ; v2(48.82,55.87) 48.9,55.95 C96.2 ; 53.63,24.09 C109.2 ; C108.2 v2(45.63,30.94) ; C108.2 45.07,30.35 ; C108.2 45.63,29.79 ; 62.23,48.35 C97.2 61.7,48.75 v2(61.62,48.67) ; 46.54,34.24 C51.2 47.1,34.8 ; 55.76,50.35 C92.2 ; C92.2 56.22,49.95 ; C92.2 56.68,50.35 ; v2(33.14,28.88) 33.23,28.96 C40.2 33.23,29.6 v2(33.14,29.68) ; v2(52.02,48.67) 52.5,49.15 C102.2 ; 57.92,39.04 C99.1 58.38,39.45 ; 55.32,53.91 C89.2 55.22,54.57 v2(55.22,55.07) ; 51.97,39.55 C59.2 52.53,40.11 ; 51.53,27.49 C110.2 ; 58.75,56.48 C95.2 58.34,55.95 v2(58.42,55.87) ; 47.52,35.13 C61.2 ; C30.2 32.45,25.78 ; C30.2 31.89,26.34 ; C30.2 31.89,25.22 ; R119.2 68.82,48.77 ; 57.23,32.29 C75.2 57.79,32.85 ; 21.64,26.43 C129.1 21.18,26.02 ; 42.86,57.6 C101.2 ; C101.2 43.42,58.16 ; C101.2 43.42,57.05 ; 76.81,27.09 C168.2 ; C142.1 97.67,43.76 ; 66.65,5.38 P1.7 ; 68.82,46.63 R120.2 ; 52.53,24.09 C67.2 ; 75.23,27.65 C154.2 75.79,27.09 ; 35.25,26.95 C128.2 ; C34.2 28.44,38.14 ; 54.02,35.59 C73.2 ; 61.25,34.99 C52.2
  BOTTOM w0.406: C106.2 v2(51.93,24.65) C67.2 ; C160.2 v2(63.03,29.74) C159.2 v2(63.03,30.95) 63.03,30.95 C50.2 ; v2(30.74,36.88) 30.74,37.47 C28.2 ; v2(51.93,39.45) 52.43,39.45 C59.2 ; v2(34.74,27.28) 34.82,27.35 C128.2 ; v2(52.33,31.35) 52.63,31.65 52.63,31.95 C72.2 ; C115.2 v2(57.14,24.65) ; C66.2 53.83,29.65 v2(53.13,28.94) ; C105.2 v2(54.34,24.65) C109.2 ; C127.2 v1(37.14,27.17)
  BOTTOM w0.508: C35.2 v1(36.45,29.87) ; v1(68.04,47.19) R120.2 ; 29.74,39.48 C126.1 ; v1(70.58,39.57) 70.27,39.25 R91.2 ; v1(73.63,50.87) R116.2 ; C142.1 97.12,44.28 v1(96.86,44.54) ; v1(71.6,42.75) R121.2 ; v2(28.35,36.88) 28.35,37.49 C34.2 ; v1(68.04,48.21) R119.2 ; C29.2 v1(26.64,37.87)
  BOTTOM w0.635: E6.1 72.56,40.84 ; E6.1 71.73,39.95 ; E6.1 71.73,41.73 ; C85.2 65.69,35.95 v1(66.94,35.95) ; C152.2 86.9,34.11 ; C152.2 86.27,34.81 ; C152.2 86.27,33.41 ; 86.27,31.89 C153.2 ; C153.2 86.27,33.28 ; C153.2 86.9,32.59
  BOTTOM w0.762: 41.71,30.37 C77.2 ; C77.2 41.71,32.47 ; C77.2 40.81,31.42 ; 68.04,26.63 68.04,27.89 ; 68.04,27.89 69.1,27.89 ; 68.04,27.89 68.04,29.14 ; 45.57,22.09 C104.2 ; C104.2 44.51,23 ; C104.2 46.62,23 ; 63.49,25.49 C103.2 62.43,24.59 ; 68.04,30.06 68.04,31.32 ; 68.04,31.32 69.1,31.32 ; 68.04,31.32 68.04,32.57 ; 19.78,24.27 C130.2 ; C130.2 19.09,24.9 ; C130.2 20.48,24.9 ; 40.17,35.75 C76.2 ; C76.2 41.22,34.49 ; C76.2 41.22,37.01 ; 48.49,22.09 C65.2 ; C65.2 49.54,23 ; C65.2 47.43,23
  vias: v1(1.6,24.71) v1(1.57,21.18) v1(2.42,48.15) v1(2.59,44.62) v1(2.59,21.18) v1(2.87,24.71) v1(3.15,58.24) v1(3.15,53.16) v1(3.15,39.19) v1(3.15,34.11) v1(3.15,16.33) v1(3.15,11.25) v1(3.69,48.15) v1(3.86,44.62) v1(3.86,21.18) v1(4.14,24.71) v1(4.96,48.15) v1(5.13,44.62) v1(5.13,21.18) v1(5.41,24.71) v1(5.69,55.7) v1(5.69,36.65) v1(5.69,31.57) v1(5.69,13.79) v1(5.69,8.71) v1(6.23,48.15) v1(6.4,44.62) v1(6.4,21.18) v1(6.68,24.71) v1(7.5,48.15) v1(7.44,21.18) v1(7.67,44.62) v1(7.92,24.96) v1(8.23,58.24) v1(8.23,53.16) v1(8.23,39.19) v1(8.23,34.11) v1(8.23,16.33) v1(8.23,11.25) v1(8.23,6.17) v1(8.64,28.55) v1(8.64,27.28) v1(8.64,26.01) v1(8.7,21.38) v1(8.77,48.15) v1(8.83,29.81) v1(8.94,44.61) v1(9.34,30.97) v1(9.83,21.95) v1(10.03,47.99) v1(10.11,44.12) v1(10.13,31.96) v1(10.77,55.7) v1(10.77,50.62) v1(10.77,41.73) v1(10.77,36.65) v1(10.77,22.81) v1(10.77,18.87) v1(10.77,13.79) v1(10.77,8.71) v1(11.22,47.55) v1(11.21,43.48) v1(11.16,32.71) v1(11.57,23.8) v1(12.05,24.98) v1(12.21,28.78) v1(12.17,27.51) v1(12.17,26.24) v1(12.32,46.92) v1(12.31,42.85) v1(12.34,33.17) v1(13.31,39.19) v1(13.31,21.41) v1(13.31,16.33) v1(13.31,11.25) v1(13.31,6.17) v1(13.42,46.28) v1(13.41,42.21) v1(13.61,33.3) v1(14.07,14.3) v1(14.2,28.01) v1(14.52,45.65) v1(14.51,41.58) v1(14.88,33.3) v1(15.09,15.31) v1(15.47,28.01) v1(15.62,45.01) v1(15.61,40.94) v1(15.85,50.62) v1(15.85,23.95) v1(15.85,18.87) v1(15.85,3.63) v1(16.1,17.35) v1(16.15,33.3) v1(16.72,44.38) v1(16.74,28.01) v1(16.86,38.3) v1(17.12,18.36) v1(17.42,33.3) v1(17.63,27.51) v1(17.82,43.74) v1(18.01,37.67) v1(18.01,17.47) v1(18.39,48.08) v1(18.69,33.3) v1(18.64,24.71) v1(18.92,43.11) v1(18.9,27.51) v1(19.02,17.47) v1(19.15,36.78) v1(19.78,35.89) v1(19.78,23.7) v1(19.91,27.51) v1(20.02,42.47) v1(19.96,33.3) v1(20.04,17.47) v1(20.67,35.38) v1(20.93,60.78) v1(20.93,50.62) v1(20.93,45.54) v1(20.93,24.71) v1(20.93,18.87) v1(20.93,3.63) v1(21.18,41.73) v1(21.18,25.73) v1(21.82,35.25) v1(22.45,40.97) v1(23.21,19.38) v1(23.47,48.08) v1(23.47,40.08) v1(23.47,16.33) v1(23.47,6.17) v1(23.59,24.33) v1(23.72,35.38) v1(24.48,38.68) v1(24.86,37.67) v1(26.01,60.78) v1(26.01,50.62) v1(26.01,3.63) v1(26.39,13.28) v1(26.52,16.08) v1(26.64,21.28) v1(27.28,48.08) v1(27.79,16.08) v1(27.79,14.81) v1(28.04,19.76) v1(29.25,39.48) v1(29.65,24.17) v1(30.2,16.84) v1(30.2,15.95) v1(30.2,15.06) v1(30.2,12.65) v1(30.2,11.5) v1(30.2,10.74) v1(30.2,9.98) v1(31.09,60.78) v1(31.09,15.06) v1(31.09,7.44) v1(31.89,25.04) v1(35.66,14.3) v1(36.68,15.31) v1(36.93,45.92) v1(37.06,49.22) v1(37.06,48.21) v1(37.56,47.32) v1(37.82,57.1) v1(37.82,54.56) v1(37.82,17.47) v1(38.45,49.98) v1(38.45,47.32) v1(38.45,44.52) v1(38.71,57.1) v1(38.71,54.56) v1(39.34,56.33) v1(39.34,55.32) v1(39.6,17.47) v1(40.49,17.47) v1(40.87,37.28) v1(41.12,34.24) v1(41.5,17.47) v1(41.76,43) v1(41.76,41.09) v1(42.39,39.57) v1(42.64,49.86) v1(43.15,56.84) v1(43.15,56.08) v1(43.41,51.25) v1(43.91,38.81) v1(45.02,9.23) v1(45.69,13.79) v1(45.83,36.01) v1(46.58,13.79) v1(47.22,60.78) v1(47.47,13.79) v1(47.6,7.44) v1(48.82,13.23) v1(49.38,16.33) v1(49.38,13.79) v1(49.82,11.73) v1(55.22,9.98) v1(55.61,17.02) v1(56.11,20.27) v1(57.12,20.27) v1(57.12,19.25) v1(57.76,65.86) v1(57.76,60.78) v1(57.76,7.44) v1(60.3,63.32) v1(60.25,20.2) v1(60.25,19.19) v1(62.03,24.44) v1(62.84,65.86) v1(62.84,60.78) v1(62.83,24.44) v1(63.42,20.2) v1(63.42,19.19) v1(64.11,57.99) v1(64.11,56.97) v1(65.12,58.62) v1(65.38,63.32) v1(66.14,58.62) v1(66.65,48.08) v1(67.41,32.84) v1(67.41,29.54) v1(67.92,65.86) v1(67.92,60.78) v1(67.92,50.62) v1(68.43,32.84) v1(68.43,29.54) v1(69.2,29.54) v1(69.44,32.84) v1(70.46,63.32) v1(70.46,58.24) v1(70.46,53.16) v1(70.71,38.43) v1(71.6,39.57) v1(71.6,38.43) v1(72.14,33.53) v1(73,65.86) v1(73,60.78) v1(73,55.7) v1(73,7.44) v1(74.14,10.74) v1(74.14,9.85) v1(75.54,46.56) v1(76.05,20.27) v1(76.05,19.12) v1(77.08,20.94) v1(78.85,19.92) v1(78.84,19.12) v1(80.05,23.74) v1(80.11,21.03) v1(81.13,63.19) v1(81.13,62.18) v1(81.13,61.29) v1(81.35,23.74) v1(81.38,20.27) v1(81.38,19.25) v1(82.14,63.19) v1(82.14,62.18) v1(82.14,61.29) v1(82.65,21.03) v1(82.75,23.74) v1(83.16,65.86) v1(83.16,63.19) v1(83.92,20.27) v1(83.92,19.25) v1(84.17,63.19) v1(84.43,56.59) v1(84.68,24.46) v1(84.85,21.04) v1(84.94,28.27) v1(85.19,63.19) v1(86.33,55.45) v1(86.33,54.56) v1(86.59,44.52) v1(86.59,43.89) v1(86.59,36.4) v1(86.71,28.27) v1(86.71,26.24) v1(86.71,22.3) v1(86.71,21.28) v1(86.71,20.27) v1(86.71,19.25) v1(86.84,53.54) v1(86.84,52.52) v1(86.84,51.51) v1(86.84,50.62) v1(87.48,32.97) v1(87.6,51.51) v1(87.6,50.62) v1(87.6,49.73) v1(87.6,48.46) v1(87.6,44.52) v1(87.6,43.89) v1(87.86,39.95) v1(87.86,39.19) v1(87.86,38.43) v1(87.86,37.54) v1(87.86,36.78) v1(88.24,65.86) v1(88.24,32.97) v1(88.49,28.27) v1(88.62,51.51) v1(88.62,49.73) v1(88.62,44.52) v1(88.62,43.89) v1(88.75,37.03) v1(89,36.14) v1(89,35.25) v1(89,34.24) v1(89,33.22) v1(89,32.2) v1(89,31.06) v1(89.51,25.98) v1(89.69,55.19) v1(90.27,25.22) v1(91.03,28.27) v1(91.03,26.24) v1(91.92,55.06) v1(91.92,54.05) v1(92.81,28.27) v1(92.81,26.24) v1(92.94,53.03) v1(93.32,65.86) v1(93.95,53.03) v1(94.59,23.95) v1(94.84,28.27) v1(94.84,26.24) v1(94.97,56.08) v1(94.97,55.06) v1(94.97,54.05) v1(94.97,53.03) v1(95.92,39.76) v1(95.98,55.06) v1(95.98,53.03) v1(96.62,28.27) v1(96.62,26.24) v1(97,55.06) v1(97.13,25.22) v1(97.64,29.54) v1(97.89,46.81) v1(98.02,55.06) v1(98.08,41.29) v1(98.14,32.59) v1(98.14,31.06) v1(98.4,27) v1(99.16,13.79) v1(99.67,28.27) v1(99.67,23.95) v1(100.68,29.54) v1(100.94,32.59) v1(100.94,31.06) v1(101.05,34) v1(101.98,20.52) v1(102.21,22.68) v1(102.21,15.06) v1(103.48,6.17) v1(106.02,16.33) v1(107.29,22.68) v1(107.8,28.9) v2(1.02,51.84) v2(1.02,50.82) v2(1.02,49.81) v2(1.02,43.08) v2(1.02,42.06) v2(1.02,41.04) v2(1.02,28.34) v2(1.02,27.33) v2(1.02,26.31) v2(1.02,19.58) v2(1.02,18.57) v2(1.02,17.55) v2(2.03,51.84) v2(2.03,50.82) v2(2.03,49.81) v2(2.03,43.08) v2(2.03,42.06) v2(2.03,41.04) v2(2.03,28.34) v2(2.03,27.33) v2(2.03,26.31) v2(2.03,19.58) v2(2.03,18.57) v2(2.03,17.55) v2(3.05,51.84) v2(3.05,50.82) v2(3.05,49.81) v2(3.05,43.08) v2(3.05,42.06) v2(3.05,41.04) v2(3.05,28.34) v2(3.05,27.33) v2(3.05,26.31) v2(3.05,19.58) v2(3.05,18.57) v2(3.05,17.55) v2(4.06,51.84) v2(4.06,50.82) v2(4.06,49.81) v2(4.06,43.08) v2(4.06,42.06) v2(4.06,41.04) v2(4.06,28.34) v2(4.06,27.33) v2(4.06,26.31) v2(4.06,19.58) v2(4.06,18.57) v2(4.06,17.55) v2(5.08,51.84) v2(5.08,50.82) v2(5.08,49.81) v2(5.08,43.08) v2(5.08,42.06) v2(5.08,41.04) v2(5.08,28.34) v2(5.08,27.33) v2(5.08,26.31) v2(5.08,19.58) v2(5.08,18.57) v2(5.08,17.55) v2(18.85,12.7) v2(18.85,11.88) v2(18.85,11.07) v2(19.66,12.7) v2(19.66,11.07) v2(20.47,12.7) v2(20.47,11.88) v2(20.47,11.07) v2(40.44,12.7) v2(40.44,11.88) v2(40.44,11.07) v2(41.25,12.7) v2(41.25,11.07) v2(41.76,32.59) v2(41.76,30.17) v2(42.06,12.7) v2(42.06,11.88) v2(42.06,11.07) v2(44.3,23.19) v2(46.72,35.05) v2(46.96,23.19) v2(49.76,23.19) v2(56.43,40.85) v2(57.13,27.15) v2(60.02,51.87) v2(60.82,51.87) v2(60.93,44.45) v2(61.25,34.95) v2(61.62,43.06) v2(61.62,42.26) v2(75.33,26.95) v2(75.33,25.73) v2(75.33,24.51) v2(75.94,26.34) v2(75.94,25.12) v2(76.55,26.95) v2(76.55,25.73) v2(76.55,24.51) v2(77.16,26.34) v2(77.16,25.12) v2(77.77,26.95) v2(77.77,25.73) v2(77.77,24.51) v2(88.76,20.57) v2(89.78,21.59) v2(89.78,19.56) v2(90.8,21.59) v2(90.8,20.57) v2(90.8,19.56) v2(90.83,45.49) v2(90.83,44.27) v2(90.83,43.05) v2(91.44,44.88) v2(91.44,43.66) v2(92.05,45.49) v2(92.05,44.27) v2(92.05,43.05) v2(92.66,44.88) v2(92.66,43.66) v2(93.27,44.27) v2(93.27,43.05)
PGND: length 16.2
  TOP w0.203: v1(101.19,52.27) 101.61,52.69 U8.C1 ; v1(99.17,39.94) 99.17,39.18 U9.C1
  TOP w0.254: 102.97,43 U16.B2 102.59,43.38
  TOP w0.305: 101.45,48.68 R69.2 102.01,49.24 ; P2.5 104.13,33.37 v1(103.88,33.12)
  TOP w0.406: P3.5 v1(103.86,51.15)
  TOP w0.635: C171.2 102.4,42.68 ; C171.2 102.4,41.28 ; C171.2 101.76,41.98 ; 102.4,39.51 C172.2 ; C172.2 101.76,40.21 ; C172.2 102.4,40.9
  TOP w0.762: 101.5,47.06 R58.2 ; R58.2 102.4,48.02 ; R58.2 102.4,46.11 ; R55.2 106.46,43.71
  BOTTOM w0.305: R67.2 101.46,46.03 v1(101.7,45.79)
  BOTTOM w0.508: v1(100.94,42.24) 101.98,42.24 Q2.2
  vias: v1(101.7,48.33) v1(101.83,41.09) v1(101.83,39.32) v1(101.95,57.22) v1(101.95,56.59) v1(101.95,55.95) v1(102.46,49.22) v1(102.46,48.33) v1(102.46,45.79) v1(102.59,57.22) v1(102.59,56.59) v1(102.59,55.95) v1(102.59,41.09) v1(102.59,39.32) v1(103.22,57.22) v1(103.22,56.59) v1(103.22,55.95) v1(106.02,44.78) v1(106.02,44.02) v1(106.91,44.78) v1(106.91,44.02)
VCCPINT: length 38.6
  TOP w0.305: U4.G6 v2(54.73,35.35) ; U4.F9 v2(56.33,32.15) ; U4.H5 v2(54.73,36.15) ; U4.G10 v2(55.53,31.35) ; 77.19,14.68 UNK1P0V.1 ; UNK1P0V.1 77.95,13.92 ; UNK1P0V.1 78.71,14.68 ; UNK1P0V.1 77.95,15.44 ; U4.E10 v2(57.13,31.35) ; U4.J10 v2(53.13,31.35) ; U4.K5 v2(52.33,36.15) ; U4.L10 v2(51.53,31.35)
  TOP w0.508: 56.99,22.13 C68.1 56.43,22.69
  TOP w0.762: C64.1 61.9,23.54 ; C64.1 60.64,22.49 ; C64.1 63.16,22.49 ; 84.14,17.79 C21.1 ; C21.1 85.19,16.89 ; C21.1 86.24,17.79 ; C71.1 58.65,23.61 ; C71.1 59.9,22.55 ; C71.1 57.39,22.55 ; 77.57,16.89 C19.1 78.62,17.79 ; 80.11,16.89 C20.1 ; C20.1 79.06,17.79 ; C20.1 81.16,17.79 ; 81.6,17.79 C17.1 ; C17.1 82.65,16.89 ; C17.1 83.7,17.79
  TOP w1.524: 85.99,16.14 L4.2 85,14.04
  BOTTOM w0.305: R7.2 84.03,16.46 v1(82.52,16.46)
  BOTTOM w0.406: v2(51.53,31.35) 51.53,31.84 C72.1 ; v2(55.53,31.35) 55.53,31.85 C74.1 55.73,32.05 56.23,32.05 v2(56.33,32.15) 56.33,32.76 C75.1 ; v2(52.33,36.15) 52.33,36.15 C73.1 ; v2(53.13,31.35) 53.83,30.64 C66.1 ; v2(54.73,36.15) 54.73,36.15 v2(54.73,35.35) 54.73,35.35 C70.1
  vias: v1(57.2,22.87) v1(57.2,22.11) v1(60.25,22.87) v1(60.25,22.11) v1(63.42,22.87) v1(63.42,22.11) v1(77.95,16.46) v1(77.95,15.69) v1(78.71,16.46) v1(78.71,15.69) v1(79.47,16.46) v1(79.47,15.69) v1(80.24,16.46) v1(80.24,15.69) v1(81,16.46) v1(81,15.69) v1(81.76,16.46) v1(81.76,15.69) v1(82.52,15.69)
VCCPLL: length 18.1
  TOP w0.305: U4.F5 v2(56.33,36.15)
  BOTTOM w0.152: 58.73,36.15 58.33,36.55 56.73,36.55 56.33,36.15 v2(56.33,36.15) 56.34,36.15 56.73,35.75 58.34,35.75 58.73,36.15
  BOTTOM w0.508: 58.73,36.15 C178.1 59.54,36.25 60.63,36.25 61.14,36.75 61.14,37.15 61.74,37.75 62.44,37.75 62.74,37.45
  BOTTOM w0.635: E1.2 68.19,36.9 67.54,37.55 65.89,37.55 C85.1 65.28,37.45 62.74,37.45
VDD33_USB: length 3
  TOP w0.305: U15.20 79.6,25.48 79.73,25.35 v1(80.36,25.35)
  BOTTOM w0.508: C165.1 79.86,24.84 v1(80.36,25.35)
VDD_INTERFACE: length 10.1
  TOP w0.305: C32.1 32.29,16.08 C33.1 ; C45.1 28.83,25.15 C43.1 v2(28.83,27.14) 28.74,27.23 U5.H12 ; C33.1 32.29,17.55 ; C33.1 32.7,17.09
  TOP w0.635: E4.2 33.25,14.93 ; E4.2 32.36,14.11 ; E4.2 34.14,14.11 ; 32.42,15.25 C32.1 33.06,15.95
  BOTTOM w0.305: C44.1 28.83,27.26 28.83,27.26 v2(28.83,27.14) 28.83,26.65 C38.1
  vias: v1(32.99,16.84) v1(33.37,15.95) v1(33.37,15.31) v1(33.63,16.84) v1(34.01,15.95) v1(34.01,15.31) v1(34.26,16.84)
VDDA1P1_RX_VCO: length 3.1
  TOP w0.305: U5.G3 v2(29.14,35.28) ; U5.G2 v2(29.14,36.08)
  BOTTOM w0.305: v2(29.15,35.28) C125.2 29.63,35.94 R51.2 29.73,36.08 v2(29.14,36.08)
VIN: length 47.7
  TOP w0.203: 36.31,52.23 U14.10 36.95,51.88
  TOP w0.305: U6.15 90.8,47.42 ; v1(91.03,40.71) 91.3,40.98 U6.27 ; R56.1 96.81,48.27 v1(97,48.46) ; v1(64.63,16.63) 64.81,16.46 C167.1 64.64,15.84 U11.8 ; C62.2 36.74,51.46 ; C62.2 36.74,50.54 ; C62.2 36.33,51 ; v1(66.39,14.74) R81.1 ; R1.2 93.9,19.57 ; R1.2 93.44,19.16 ; R1.2 92.99,19.57 ; C164.1 80.8,25.98 v1(79.86,25.98) U15.21 ; 91.75,19.16 U3.13 92.5,19.6 ; 89.76,41.48 90.02,41.73 90.21,41.73 U6.25 90.3,41.12 ; 89.78,47.04 89.98,46.84 90.18,46.84 U6.16 90.3,47.42 ; 91.3,47.56 U6.14 ; 91.62,16.14 C8.1 91.16,16.55 ; 91.19,18.6 U3.12 90.76,17.85 ; v1(66.39,13.22) R80.1 ; 90.8,41.12 U6.26
  TOP w0.508: C169.1 50.88,13.23 ; C169.1 50.88,12.06 ; C169.1 51.43,12.65 ; DS1.A v1(106.78,19.29) ; DS2.A v1(106.91,10.91)
  TOP w0.635: 91.98,16.39 C9.1 ; C9.1 92.68,17.03 ; C9.1 93.38,16.39
  TOP w0.762: C135.1 90.21,40.4 ; C135.1 90.21,39 ; C135.1 90.84,39.7 ; C137.1 90.84,37.92 ; C137.1 90.21,38.62 ; C137.1 90.21,37.22 ; C138.1 90.59,50.62 ; C138.1 89.95,51.32 ; C138.1 89.95,49.92 ; C157.1 85.05,59 ; C157.1 83.79,57.95 ; C157.1 82.54,59 ; 89.95,48.14 C136.1 ; C136.1 90.59,48.84 ; C136.1 89.95,49.54 ; 86.61,58.32 Q3.2 85.66,59.08 ; 51.92,13.6 E2.1 52.8,12.77
  TOP w1.016: 93.91,16.65 C11.1 94.97,17.55
  BOTTOM w0.305: R6.1 v1(92.94,18.11) ; R222.1 R221.1 v1(35.79,51)
  BOTTOM w0.406: v1(91.67,38.94) 92.42,38.94 R59.2 ; v1(91.03,38.94) 90.16,38.94 R85.1
  vias: v1(35.79,50.24) v1(36.42,50.24) v1(52.04,12.52) v1(52.04,11.76) v1(52.93,12.52) v1(52.93,11.76) v1(80.24,59.51) v1(80.24,58.87) v1(80.24,58.24) v1(80.87,59.51) v1(80.87,58.87) v1(80.87,58.24) v1(81.51,59.51) v1(81.51,58.87) v1(81.51,58.24) v1(82.14,59.51) v1(82.14,58.87) v1(82.14,58.24) v1(90.4,52.14) v1(90.4,51.51) v1(90.4,37.03) v1(90.4,36.4) v1(90.78,50.87) v1(90.78,50.24) v1(90.78,49.6) v1(91.03,52.14) v1(91.03,51.51) v1(91.03,38.3) v1(91.03,37.67) v1(91.03,37.03) v1(91.03,36.4) v1(91.03,17.47) v1(91.03,16.84) v1(91.41,50.87) v1(91.41,50.24) v1(91.41,49.6) v1(91.67,52.14) v1(91.67,51.51) v1(91.67,38.3) v1(91.67,37.67) v1(91.67,37.03) v1(91.67,36.4) v1(91.67,17.47) v1(91.67,16.84) v1(92.3,18.11) v1(92.3,17.47) v1(92.94,17.47) v1(93.57,18.11) v1(93.57,17.47) v1(94.21,18.11) v1(94.84,18.11)
VIN_5V_USB: length 3.7
  TOP w0.254: U9.A1 U9.B1 99.79,39.44 ; U9.A1 100.68,39.06 ; U9.A1 100.29,39.44 ; U8.A1 U8.B1 101.52,53.19 ; U8.A1 101.29,53.69 v1(101.19,53.79) ; U8.A1 101.9,54.13
  vias: v1(99.92,39.95) v1(100.05,41.22) v1(100.05,40.59) v1(100.56,54.43) v1(100.56,53.79) v1(100.56,53.16) v1(100.56,39.95) v1(100.68,41.22) v1(100.68,40.59) v1(101.19,54.43) v1(101.19,53.16) v1(101.95,60.91) v1(101.95,60.27) v1(101.95,59.64) v1(101.95,59) v1(102.59,60.91) v1(102.59,60.27) v1(102.59,59.64) v1(102.59,59)
VIN_5V_USB_DATA: length 9.8
  TOP w0.203: 99.91,37.93 99.79,38.05 98.26,38.05 R70.1
  TOP w0.254: 100.29,38.18 U9.A2 ; U9.A2 U9.B2 99.79,38.05 ; U9.A2 100.68,38.56
  TOP w0.406: P2.1 103.84,35.97 102.53,37.28 v1(100.56,37.28)
  BOTTOM w0.508: 101.69,38.3 F1.2 102.23,37.69
  vias: v1(99.92,37.92) v1(99.92,37.28) v1(100.56,37.92)
VIN_5V_USB_POWER: length 8.1
  TOP w0.203: R68.1 102.96,52.13 103.22,52.4 103.22,53.16
  TOP w0.254: U8.A2 U8.B2 102.78,53.19 ; U8.A2 102.78,53.69 ; U8.A2 102.4,54.07 ; 103.47,44.27 U16.A1 103.86,43.88
  TOP w0.406: P3.1 103.86,53.75
  L5_SIG w0.635: v1(103.11,53.45) v1(103.11,54.21)
  BOTTOM w0.305: v1(104.49,44.78) 104.48,44.79 R66.1
  vias: v1(104.49,44.02)
1P3_SUPPLY_A: length 71.7
  TOP w0.203: 41.57,14.56 41.69,14.68 42.06,14.68 42.22,14.51 U7.9
  TOP w0.305: U5.B10 v2(33.94,28.88) ; C18.1 41.96,16.14 ; C18.1 41.5,15.73 ; C18.1 41.04,16.14 ; U7.11 U7.12 ; U7.11 U7.10 41.57,14.56 ; U7.11 40.92,14.56 ; U7.12 39.84,13.78 ; U7.12 40.27,14.56 ; 38.57,12.86 U7.13 ; U7.13 39.35,13.29 ; U7.13 U7.14 38.57,12.21 ; C16.1 40.69,16.14 ; C16.1 40.23,15.73 ; C16.1 39.77,16.14 ; 42.39,16.33 UNK1P3V_A.1 43.15,15.57 ; U5.K3 v2(26.74,35.28) ; U5.F2 v2(30.74,36.08) ; U5.J3 v2(27.55,35.28) ; U5.E2 v2(31.54,36.08) ; U5.B9 v2(33.94,29.68)
  TOP w0.635: C15.1 38.52,14.3 ; C15.1 37.88,13.6 ; C15.1 37.88,15 ; 38.71,15.38 C14.1 ; C14.1 38.01,16.01 ; C14.1 39.41,16.01
  BOTTOM w0.305: v2(33.94,28.88) 33.86,28.96 C40.1 33.86,29.6 v2(33.94,29.68) ; C28.1 31.84,37.47 31.33,36.96 C23.1 31.33,36.2 31.46,36.08 ; 31.46,36.08 v2(31.54,36.08) ; 31.46,36.08 v2(30.74,36.08) ; C29.1 26.26,36.57 C24.1 26.49,35.64 26.49,35.53 v2(26.74,35.28) ; 27.45,36.58 27.33,36.46 C39.1 27.33,35.5 v2(27.55,35.28)
  BOTTOM w0.406: v2(33.94,28.88) 33.95,28.88 C35.1
  BOTTOM w0.508: v1(28.67,46.94) v1(28.67,46.17) 27.45,44.95 C34.1 27.45,36.58 ; v1(24.74,45.85) v1(24.74,45.05) 24.36,44.67 24.36,39.82 23.47,38.94 23.47,37.92 24.5,36.88 C29.1 ; C28.1 v1(31.84,46.07) v1(31.84,46.87)
  BOTTOM w0.635: v1(37.85,20.27) v1(38.71,20.27) 38.71,20.28 38.71,27.76 37.59,28.88 C35.1
  vias: v1(37.82,16.08) v1(37.82,15.19) v1(38.71,15.19) v1(38.83,14.3) v1(39.6,16.08) v1(39.6,15.19) v1(40.87,16.08) v1(42.14,16.08)
